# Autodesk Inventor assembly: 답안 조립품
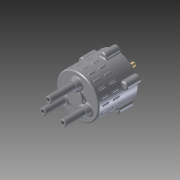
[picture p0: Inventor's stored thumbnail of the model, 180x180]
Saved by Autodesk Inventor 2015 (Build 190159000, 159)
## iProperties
Created: 2016-01
Part Number: 답안 조립품
Document SubType Name: Assembly
Designer: 601-23
Author: 601-23
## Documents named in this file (14)
- C:\Users\601-23\Desktop\360106V1012\답안 조립품.iam
- C:\Users\601-23\Desktop\360106V1012\본체.ipt
- C:\Users\601-23\Desktop\360106V1012\슬라이드 축.ipt
- C:\Users\601-23\Desktop\360106V1012\커버.ipt
- C:\Users\601-23\Desktop\360106V1012\판캠.ipt
- C:\Users\601-23\Desktop\360106V1012\베어링 NA 4900.ipt
- C:\Users\601-23\Desktop\360106V1012\메인 축.ipt
- C:\Users\601-23\Desktop\360106V1012\멈춤링 22 x 1.2.ipt
- C:\Users\601-23\Desktop\360106V1012\오일실.ipt
- C:\Users\601-23\Desktop\360106V1012\멈춤링 10 x 1.ipt
- C:\Users\601-23\Desktop\360106V1012\스프링1.ipt
- C:\Users\601-23\Desktop\360106V1012\스프링2.ipt
- C:\Users\601-23\Desktop\360106V1012\스프링3.ipt
- C:\Users\601-23\Desktop\360106V1012\M5x0.8x20.ipt
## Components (5 placed, 1 different names)
1. M5x0.8x20:1
2. M5x0.8x20:2
3. M5x0.8x20:3
4. M5x0.8x20:4
5. M5x0.8x20:5 — 각도:2
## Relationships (1: Angle 1)
- 각도:2 [Angle]: M5x0.8x20:5
